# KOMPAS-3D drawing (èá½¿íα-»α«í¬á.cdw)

Referenced files: Калибр-пробка.cdw
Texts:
  Калибр-пробка 36Н7$m(+0.025);$
  http://freecads.ru/
  изн.  35,997
  Рифление сетчатое Т1
  ГОСТ 21474-75
  Ra 0,8
  2.Покрытие рабочих поверхностей Хр0.6, нерабочих поверх-
  ностей - Хим.Фос.Прм.
  3.Технические требования по ГОСТ 2015-84.
  4.Маркировать: 36Н7 (+0.025) .
  5.Неуказанные предельные отклонения  IT14 2 .
  Ra 12.5
  Калибр-пробка
Dimensions and other numbers on the sheet: 36,027; 36,005; 36; 56; 6; 2 фаски; 40; 58; 150; 24; 42; 0,4; 4 фаски; 1.57...65 HRCэ.; 36Н7 (+0.025); 2:1; 1; 0; 2; 3; 4; 5; 7; 8; 9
